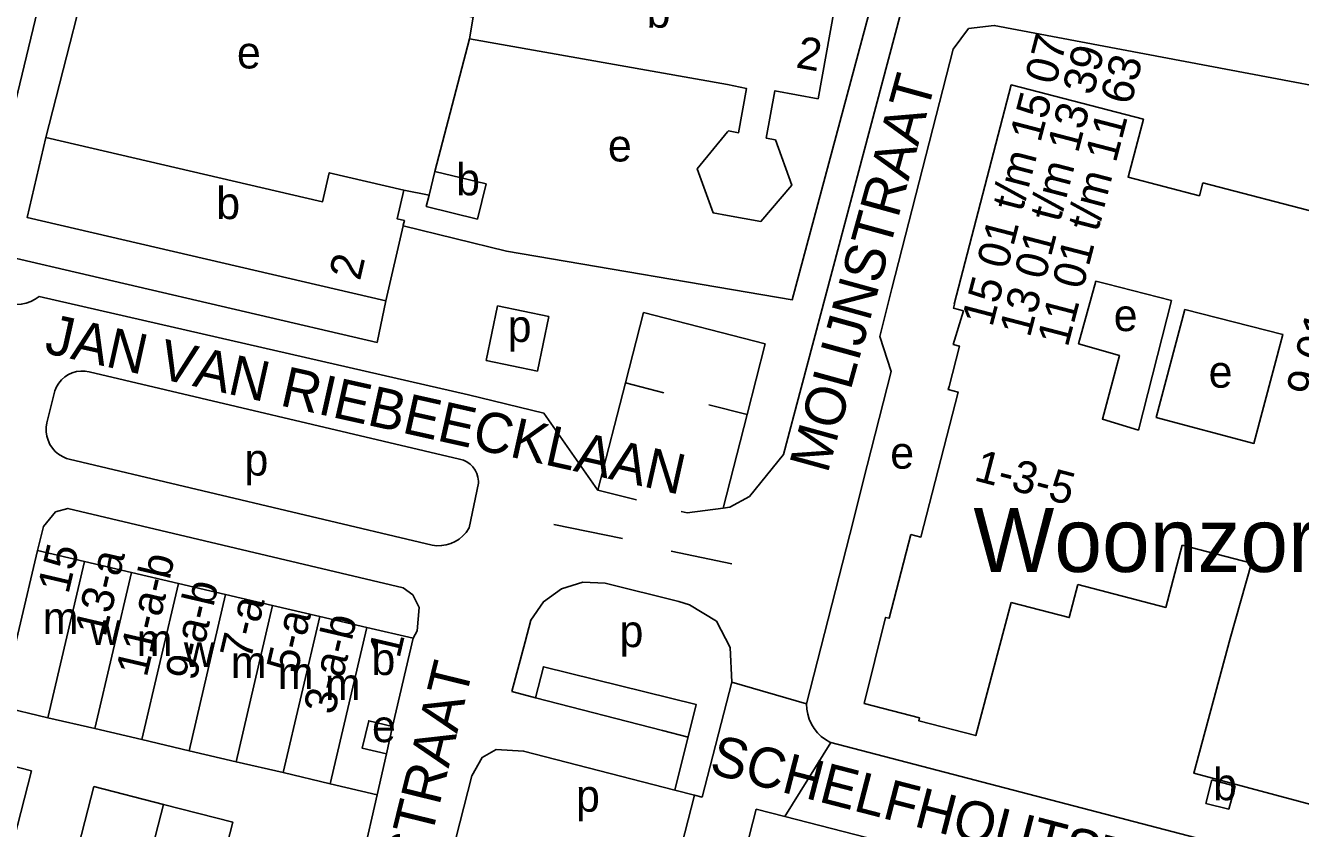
# Model space of a CAD drawing. Extents: x 163012 to 165277, y 382513 to 383987.
# Drawn here: x 163912.4 to 164071.5, y 383275.8 to 383376 of the extents above; entities that cross this region are included whole.
import ezdxf

# ---------------------------------------------------------------- set-up
doc = ezdxf.new("R2010")
doc.units = 0
for name, color, linetype in [('BLT_Basislijn', 7, 'Continuous'), ('BLT_Bebouwing', 7, 'Continuous'), ('BLT_Bebouwing_beschrifting', 7, 'Continuous'), ('BLT_Centroide', 7, 'Continuous'), ('BLT_Huisnummer', 7, 'Continuous'), ('BLT_Huisnummer_reeks', 7, 'Continuous'), ('BLT_Onderverdeling_panden', 7, 'Continuous'), ('BLT_Straatnaam', 7, 'Continuous'), ('BLT_Vlakafsluiter', 7, 'Continuous')]:
    doc.layers.add(name, color=color, linetype=linetype)

msp = doc.modelspace()

# ---------------------------------------------------------------- linework, layer by layer
at = {"layer": 'BLT_Basislijn'}
for p, q in [((164021.64, 383377.78), (164009.18, 383330.82)), ((163967.81, 383374.39), (163963.49, 383357.83)), ((164028.12, 383373.09), (164020.51, 383343.23)), ((163962.77, 383354.86), (163959.62, 383355.5)), ((163972.43, 383347.89), (163959.53, 383351.02)), ((163914.14, 383342.22), (163967.7, 383329.93)), ((164020.51, 383343.23), (164019.27, 383338.39)), ((163957.36, 383341.67), (163956.29, 383336.46)), ((163969.91, 383334.22), (163971.32, 383341.05)), ((163971.32, 383341.05), (163977.72, 383339.74)), ((164028.31, 383341.26), (164028.26, 383341.28)), ((163977.72, 383339.74), (163976.31, 383332.9)), ((163989.52, 383340.23), (163987.26, 383331.43)), ((164004.7, 383336.31), (163989.52, 383340.23)), ((164019.27, 383338.39), (164018.98, 383337.23)), ((164018.98, 383337.23), (164020.42, 383332.85)), ((164002.44, 383327.47), (164004.7, 383336.31)), ((163976.31, 383332.9), (163969.91, 383334.22)), ((163920.38, 383332.81), (163966.58, 383321.92)), ((164020.42, 383332.85), (164016.93, 383319.17)), ((163987.26, 383331.43), (163983.84, 383318.05)), ((163992.05, 383330.2), (163987.26, 383331.43)), ((163915.99, 383329.95), (163915.09, 383326.45)), ((163997.66, 383328.7), (164002.44, 383327.47)), ((163999.45, 383315.82), (164002.44, 383327.47)), ((163963.15, 383311.18), (163917.87, 383321.91)), ((163968.94, 383318.92), (163967.76, 383313.33)), ((164016.93, 383319.17), (164015.69, 383314.32)), ((163983.84, 383318.05), (163988.64, 383316.83)), ((163978.34, 383313.78), (163986.88, 383312.01)), ((164015.69, 383314.32), (164009.84, 383291.37)), ((163992.97, 383310.42), (164000.52, 383308.86)), ((163973.08, 383292.91), (163976.06, 383292.14)), ((163976.06, 383292.14), (163991.88, 383288.06)), ((163958.2, 383288.57), (163957.48, 383285.12)), ((164012.88, 383286.54), (164069.56, 383271.77)), ((163949.86, 383251.46), (163956.29, 383280.04)), ((163995.86, 383279.99), (163992.76, 383267.91)), ((163993.43, 383280.61), (163995.86, 383279.99))]:
    msp.add_line(p, q, dxfattribs=at)
for points in [[(163906.92, 383348.35), (163906.88, 383348.73), (163907.35, 383350.8), (163918.78, 383398.18), (164018.58, 383381.08)], [(163966.78, 383378.58), (163921.84, 383388.9), (163914.98, 383362.07)], [(164018.58, 383381.08), (164008.06, 383341.81), (163972.43, 383347.89)], [(164028.12, 383373.09), (164030.07, 383375.66), (164033.27, 383376.04), (164110.45, 383361.47), (164125.7, 383361.18)], [(163956.29, 383336.46), (163906.97, 383347.96), (163906.92, 383348.35)], [(163908.9, 383341.8), (163909.46, 383341.54), (163910.05, 383341.36), (163910.66, 383341.24), (163911.28, 383341.22), (163911.9, 383341.26), (163912.5, 383341.39), (163913.09, 383341.6), (163913.64, 383341.88), (163914.14, 383342.22)], [(163920.38, 383332.81), (163919.85, 383332.9), (163919.32, 383332.91), (163918.79, 383332.84), (163918.27, 383332.7), (163917.78, 383332.47), (163917.34, 383332.18), (163916.94, 383331.82), (163916.6, 383331.41), (163916.32, 383330.95), (163916.11, 383330.46), (163915.99, 383329.95)], [(163999.45, 383315.82), (164000.29, 383315.93), (164002.74, 383317.27), (164006.97, 383322.49), (164009.18, 383330.82)], [(163967.7, 383329.93), (163977.1, 383327.65), (163983.77, 383318.07), (163983.84, 383318.05)], [(163915.09, 383326.45), (163915.01, 383325.9), (163915.01, 383325.34), (163915.09, 383324.8), (163915.25, 383324.27), (163915.48, 383323.76), (163915.79, 383323.3), (163916.15, 383322.88), (163916.57, 383322.53), (163917.04, 383322.23), (163917.55, 383322.01), (163917.87, 383321.91)], [(163966.58, 383321.92), (163967.05, 383321.78), (163967.48, 383321.57), (163967.88, 383321.29), (163968.23, 383320.95), (163968.51, 383320.56), (163968.73, 383320.13), (163968.87, 383319.66), (163968.93, 383319.18), (163968.94, 383318.92)], [(163913.94, 383310.53), (163914.69, 383313.52), (163916.18, 383315.33), (163917.73, 383315.77), (163959.56, 383305.86), (163960.74, 383304.97), (163961.52, 383303.41), (163961.29, 383300.5), (163960.78, 383299.56)], [(163994.22, 383315.4), (163994.95, 383315.22), (163999.45, 383315.82)], [(163963.15, 383311.18), (163963.74, 383311.11), (163964.33, 383311.12), (163964.92, 383311.22), (163965.48, 383311.39), (163966.02, 383311.63), (163966.52, 383311.95), (163966.98, 383312.33), (163967.38, 383312.77), (163967.76, 383313.33)], [(164000.54, 383294.08), (164000.34, 383298.43), (163998.62, 383301.71), (163995.27, 383303.72), (163993.91, 383304.16), (163984.73, 383306.45), (163981.95, 383306.55), (163979.28, 383305.75), (163977.03, 383304.12), (163975.47, 383301.82), (163974.75, 383299.13), (163973.08, 383292.91)], [(163976.06, 383292.14), (163977.04, 383296.01), (163996.09, 383291.28), (163993.43, 383280.61)], [(163995.86, 383279.99), (163996.83, 383279.74), (164000.54, 383294.08)], [(164009.84, 383291.37), (164009.88, 383290.71), (164010, 383290.07), (164010.2, 383289.45), (164010.47, 383288.85), (164010.81, 383288.29), (164011.22, 383287.78), (164011.69, 383287.32), (164012.21, 383286.92), (164012.77, 383286.59), (164012.88, 383286.54)], [(163991.88, 383288.06), (163995.08, 383287.23)], [(163971.16, 383285.7), (163969.38, 383284.7), (163968.12, 383282.39), (163966.09, 383274.58)], [(163971.16, 383285.7), (163974.57, 383285.48), (163993.43, 383280.61)], [(164007.14, 383277.33), (164003.58, 383278.22), (164001.41, 383269.77)], [(164007.14, 383277.33), (164056.6, 383264.59), (164057.3, 383263.86), (164050.54, 383237.47), (164033.31, 383170.81), (164031.68, 383169.14), (164030.33, 383168.38), (164029.1, 383168.33)]]:
    msp.add_lwpolyline(points, dxfattribs=at)
at = {"layer": 'BLT_Bebouwing'}
for p, q in [((164000, 383368.68), (163967.81, 383374.39)), ((163963.49, 383357.83), (163962.77, 383354.86)), ((163959.53, 383351.02), (163957.36, 383341.67)), ((163913.94, 383310.53), (163909.37, 383291.03)), ((163919.8, 383309.16), (163913.94, 383310.53)), ((163925.67, 383307.79), (163919.8, 383309.16)), ((163931.53, 383306.41), (163925.67, 383307.79)), ((163937.4, 383305.04), (163931.53, 383306.41)), ((163943.26, 383303.67), (163937.4, 383305.04)), ((163949.13, 383302.29), (163943.26, 383303.67)), ((163954.99, 383300.92), (163949.13, 383302.29)), ((163960.78, 383299.56), (163954.99, 383300.92)), ((163958.2, 383288.57), (163960.78, 383299.56)), ((163909.37, 383291.03), (163915.24, 383289.65)), ((163932.83, 383285.53), (163938.7, 383284.16)), ((163956.29, 383280.04), (163957.48, 383285.12)), ((163938.7, 383284.16), (163944.56, 383282.79)), ((163944.56, 383282.79), (163950.43, 383281.41)), ((164060.4, 383281.9), (164059.67, 383278.96)), ((164063.3, 383281.11), (164060.4, 383281.9)), ((163950.43, 383281.41), (163956.29, 383280.04)), ((164062.54, 383278.23), (164063.3, 383281.11)), ((164059.67, 383278.96), (164062.54, 383278.23))]:
    msp.add_line(p, q, dxfattribs=at)
for points in [[(163967.81, 383374.39), (163968.29, 383377.1), (163966.51, 383377.42), (163966.78, 383378.58)], [(164000, 383379.27), (164004.15, 383378.51), (164004.34, 383379.57), (164013.31, 383377.95), (164011.3, 383366.9), (164005.9, 383367.89), (164004.83, 383361.98), (164005.98, 383361.77), (164008, 383356.11), (164004.17, 383351.59), (164000, 383352.33)], [(164000, 383368.68), (164002.37, 383368.17), (164001.37, 383362.65), (164000.1, 383362.88), (164000, 383362.76)], [(164028.26, 383341.28), (164035.39, 383368.62), (164051.86, 383364.33), (164049.96, 383357.12), (164058.86, 383354.8), (164059.28, 383356.4), (164074.27, 383352.49)], [(164000, 383362.76), (163996.19, 383358.17), (163998.22, 383352.64), (164000, 383352.33)], [(163957.36, 383341.67), (163912.65, 383352.06), (163914.98, 383362.07)], [(163914.98, 383362.07), (163949.49, 383354.05), (163950.33, 383357.66), (163959.62, 383355.5)], [(163968.8, 383351.88), (163969.88, 383356.27), (163963.49, 383357.83)], [(163959.62, 383355.5), (163958.79, 383351.92), (163959.69, 383351.71), (163959.56, 383351.12), (163959.53, 383351.02)], [(163962.77, 383354.86), (163962.42, 383353.45), (163968.8, 383351.88)], [(164027.62, 383331), (164028.92, 383336.03), (164028.16, 383336.24), (164029.43, 383340.44)], [(164029.43, 383340.44), (164028.18, 383340.77), (164028.31, 383341.26)], [(164022.86, 383312.52), (164024.11, 383312.2), (164028.77, 383330.26), (164027.51, 383330.59), (164027.62, 383331)], [(164017.02, 383291.42), (164019.71, 383302.17), (164020.15, 383302.06), (164022.86, 383312.52)], [(164056.69, 383311.19), (164054.66, 383303.41), (164043.68, 383306.27)], [(164056.69, 383311.19), (164065.35, 383308.94)], [(164074.78, 383278.27), (164058.14, 383282.71), (164062.68, 383299.54), (164065.35, 383308.94)], [(164043.68, 383306.27), (164042.61, 383302.15), (164035.38, 383304.03)], [(164035.38, 383304.03), (164030.96, 383287.41), (164023.84, 383289.26), (164023.93, 383289.62), (164017.02, 383291.42)], [(163915.24, 383289.65), (163921.1, 383288.28)], [(163921.1, 383288.28), (163926.96, 383286.91)], [(163957.48, 383285.12), (163954.43, 383285.83), (163955.24, 383289.27), (163958.2, 383288.57)], [(163926.96, 383286.91), (163932.83, 383285.53)], [(163907.87, 383262.37), (163913.18, 383283.01), (163907.14, 383284.56)], [(163929.64, 383278.82), (163920.96, 383281.05), (163915.64, 383260.36)], [(163932.99, 383255.89), (163938.31, 383276.59), (163929.64, 383278.82)]]:
    msp.add_lwpolyline(points, dxfattribs=at)
for points in [[(164055.36, 383341.7), (164047.28, 383343.78), (164045.94, 383344.12), (164043.79, 383336.31), (164048.88, 383334.87), (164046.76, 383326.91), (164051.25, 383325.55)], [(164057.04, 383340.59), (164053.47, 383327.11), (164065.65, 383323.88), (164069.26, 383337.48)]]:
    msp.add_lwpolyline(points, close=True, dxfattribs=at)
at = {"layer": 'BLT_Onderverdeling_panden'}
for p, q in [((163915.24, 383289.65), (163919.8, 383309.16)), ((163921.1, 383288.28), (163925.67, 383307.79)), ((163926.96, 383286.91), (163931.53, 383306.41)), ((163932.83, 383285.53), (163937.4, 383305.04)), ((163938.7, 383284.16), (163943.26, 383303.67)), ((163944.56, 383282.79), (163949.13, 383302.29)), ((163950.43, 383281.41), (163954.99, 383300.92)), ((163929.64, 383278.82), (163924.31, 383258.12))]:
    msp.add_line(p, q, dxfattribs=at)
at = {"layer": 'BLT_Vlakafsluiter'}
for p, q in [((164009.84, 383291.37), (164000.54, 383294.08)), ((164007.14, 383277.33), (164012.88, 383286.54))]:
    msp.add_line(p, q, dxfattribs=at)

# ---------------------------------------------------------------- texts
at = {"layer": 'BLT_Bebouwing_beschrifting'}
msp.add_text('Woonzorgcentrum', height=8, dxfattribs=at).set_placement((164030.66, 383307.84))
at = {"layer": 'BLT_Centroide'}
for s, p in [('b', (163989.91, 383375.77)), ('e', (163938.81, 383370.68)), ('e', (163985.08, 383359.07)), ('b', (163966.15, 383354.84)), ('b', (163936.23, 383351.88)), ('e', (164048.16, 383337.9)), ('p', (163972.58, 383336.55)), ('e', (164060, 383330.84)), ('p', (163939.75, 383319.87)), ('e', (164020.29, 383320.73)), ('m', (163914.59, 383300.09)), ('w', (163920.45, 383298.72)), ('p', (163986.53, 383298.46)), ('m', (163926.31, 383297.34)), ('w', (163932.19, 383295.97)), ('b', (163955.59, 383294.98)), ('m', (163938.05, 383294.59)), ('m', (163943.91, 383293.22)), ('m', (163949.78, 383291.84)), ('e', (163955.65, 383286.6)), ('b', (164060.56, 383279.35)), ('p', (163981.1, 383277.92))]:
    msp.add_text(s, height=4, dxfattribs=at).set_placement(p)
at = {"layer": 'BLT_Huisnummer'}
for s, rotation, p in [('2', 349.7054, (164008.4, 383370.83)), ('2', 76.9173, (163954.15, 383344.09)), ('15', 76.8183, (163917.78, 383304.97)), ('1', 76.8194, (163959.07, 383296.94))]:
    msp.add_text(s, height=4, rotation=rotation, dxfattribs=at).set_placement(p)
at = {"layer": 'BLT_Huisnummer_reeks'}
for s, rotation, p in [('15 01 t/m 15 07', 75.3874, (164033.01, 383338.3)), ('13 01 t/m 13 39', 75.3874, (164037.7, 383336.99)), ('11 01 t/m 11 63', 75.3874, (164042.42, 383335.78)), ('9 01 t/m 9 89', 75.3874, (164073.47, 383329.55)), ('1-3-5', 345.3872, (164030.6, 383319.3)), ('13-a', 76.8183, (163922.42, 383299.62)), ('11-a-b', 76.8192, (163927.55, 383294.59)), ('9-a-b', 76.8225, (163933.69, 383294.12)), ('7-a', 76.8197, (163940.52, 383296.73)), ('5-a', 76.8219, (163946.31, 383295.05)), ('3-a-b', 76.8212, (163950.95, 383289.89))]:
    msp.add_text(s, height=4, rotation=rotation, dxfattribs=at).set_placement(p)
at = {"layer": 'BLT_Straatnaam'}
for s, rotation, p in [('JAN GOSSAERTSTRAAT', 75.7373, (163900.11, 383334.93)), ('MOLIJNSTRAAT', 74.5838, (164012.47, 383320.01)), ('JAN VAN RIEBEECKLAAN', 347.4096, (163914.65, 383335.21)), ('GERARD DAVIDSTRAAT', 76.1638, (163949.83, 383220.86)), ('SCHELFHOUTSTRAAT', 345.4821, (163997.56, 383282.75))]:
    msp.add_text(s, height=5, rotation=rotation, dxfattribs=at).set_placement(p)

doc.saveas('drawing.dxf')
